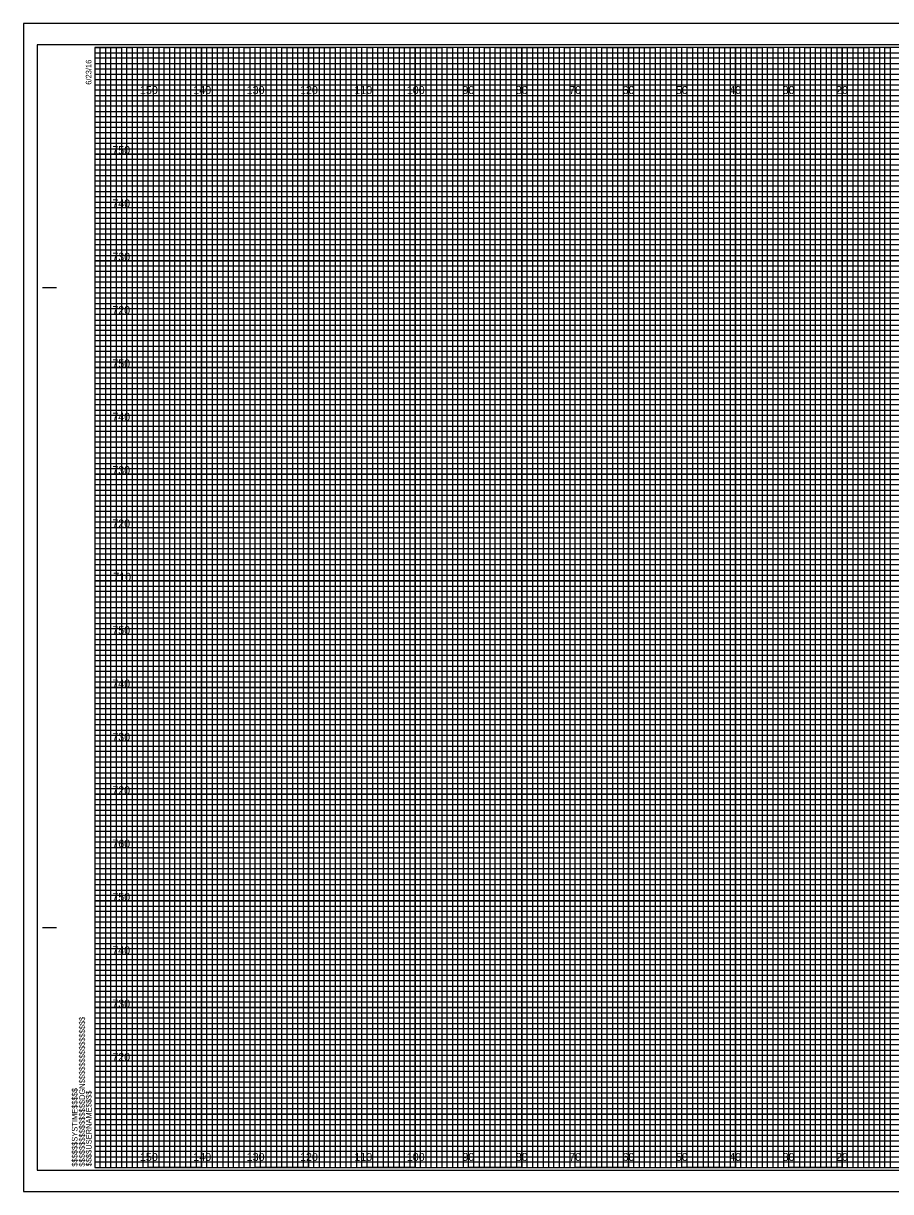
# Model space of a CAD drawing. Extents: x -13 to 323, y 655 to 874.
# Drawn here: x -13.4 to 149.1, y 655.5 to 874.5 of the extents above; entities that cross this region are included whole.
import ezdxf

# ---------------------------------------------------------------- set-up
doc = ezdxf.new("R2010")
doc.units = 0
for name, color, linetype in [('Prop CMT Guardrail Graphics', 7, 'Continuous'), ('Prop XS DDE', 7, 'Continuous'), ('Prop XS DDE Elevations', 7, 'Continuous'), ('Prop XS DDE Text', 7, 'Continuous'), ('Prop XS Hydro Elevations', 7, 'Continuous'), ('Prop XS Hydro Slope Text', 7, 'Continuous'), ('Prop XS Hydro Typical Ditch Data', 7, 'Continuous'), ('Prop XS SE Text', 7, 'Continuous'), ('Prop XS Undercut Exc', 7, 'Continuous'), ('Scratch_Level_1', 7, 'Continuous'), ('Scratch_Level_4', 7, 'Continuous')]:
    doc.layers.add(name, color=color, linetype=linetype)

msp = doc.modelspace()

# ---------------------------------------------------------------- linework, layer by layer
at = {"layer": 'Prop CMT Guardrail Graphics'}
for p, q in [((10, 870), (0, 870)), ((10, 660), (10, 870)), ((30, 870), (20, 870)), ((20, 870), (20, 660)), ((30, 660), (30, 870)), ((50, 870), (40, 870)), ((40, 870), (40, 660)), ((50, 660), (50, 870)), ((70, 870), (60, 870)), ((60, 870), (60, 660)), ((70, 660), (70, 870)), ((90, 870), (80, 870)), ((80, 870), (80, 660)), ((90, 660), (90, 870)), ((110, 870), (100, 870)), ((100, 870), (100, 660)), ((110, 660), (110, 870)), ((130, 870), (120, 870)), ((120, 870), (120, 660)), ((130, 660), (130, 870)), ((150, 870), (140, 870)), ((140, 870), (140, 660)), ((20, 660), (10, 660)), ((40, 660), (30, 660)), ((60, 660), (50, 660)), ((80, 660), (70, 660)), ((100, 660), (90, 660)), ((120, 660), (110, 660)), ((140, 660), (130, 660))]:
    msp.add_line(p, q, dxfattribs=at)
for points in [[(0, 860), (320, 860), (320, 850), (0, 850)], [(0, 840), (320, 840), (320, 830), (0, 830)], [(0, 820), (320, 820), (320, 810), (0, 810)], [(0, 800), (320, 800), (320, 790), (0, 790)], [(0, 780), (320, 780), (320, 770), (0, 770)], [(0, 760), (320, 760), (320, 750), (0, 750)], [(0, 740), (320, 740), (320, 730), (0, 730)], [(0, 720), (320, 720), (320, 710), (0, 710)], [(0, 700), (320, 700), (320, 690), (0, 690)], [(0, 680), (320, 680), (320, 670), (0, 670)]]:
    msp.add_lwpolyline(points, dxfattribs=at)
at = {"layer": 'Prop XS DDE'}
msp.add_lwpolyline([(-10.8, 659.5), (322.4, 659.5), (322.4, 870.5), (-10.8, 870.5)], close=True, dxfattribs=at)
at = {"layer": 'Prop XS DDE Elevations'}
for p, q in [((323.3, 874.5), (-13.4, 874.5)), ((-13.4, 874.5), (-13.4, 655.5)), ((-13.4, 655.5), (323.3, 655.5))]:
    msp.add_line(p, q, dxfattribs=at)
at = {"layer": 'Prop XS DDE Text'}
for p, q in [((10, 660), (10, 870)), ((20, 660), (20, 870)), ((30, 660), (30, 870)), ((40, 660), (40, 870)), ((50, 660), (50, 870)), ((60, 660), (60, 870)), ((70, 660), (70, 870)), ((80, 660), (80, 870)), ((90, 660), (90, 870)), ((100, 660), (100, 870)), ((110, 660), (110, 870)), ((120, 660), (120, 870)), ((130, 660), (130, 870)), ((140, 660), (140, 870)), ((0, 860), (320, 860)), ((0, 850), (320, 850)), ((0, 840), (320, 840)), ((0, 830), (320, 830)), ((0, 820), (320, 820)), ((0, 810), (320, 810)), ((0, 800), (320, 800)), ((0, 790), (320, 790)), ((0, 780), (320, 780)), ((0, 770), (320, 770)), ((0, 760), (320, 760)), ((0, 750), (320, 750)), ((0, 740), (320, 740)), ((0, 730), (320, 730)), ((0, 720), (320, 720)), ((0, 710), (320, 710)), ((0, 700), (320, 700)), ((0, 690), (320, 690)), ((0, 680), (320, 680)), ((0, 670), (320, 670))]:
    msp.add_line(p, q, dxfattribs=at)
at = {"layer": 'Prop XS Hydro Elevations'}
for points in [[(0, 660), (1, 660), (1, 870), (2, 870), (2, 660)], [(2, 660), (3, 660), (3, 870), (4, 870), (4, 660)], [(5, 660), (6, 660), (6, 870), (7, 870), (7, 660)], [(7, 660), (8, 660), (8, 870), (9, 870), (9, 660)], [(10, 660), (11, 660), (11, 870), (12, 870), (12, 660)], [(12, 660), (13, 660), (13, 870), (14, 870), (14, 660)], [(15, 660), (16, 660), (16, 870), (17, 870), (17, 660)], [(17, 660), (18, 660), (18, 870), (19, 870), (19, 660)], [(20, 660), (21, 660), (21, 870), (22, 870), (22, 660)], [(22, 660), (23, 660), (23, 870), (24, 870), (24, 660)], [(25, 660), (26, 660), (26, 870), (27, 870), (27, 660)], [(27, 660), (28, 660), (28, 870), (29, 870), (29, 660)], [(30, 660), (31, 660), (31, 870), (32, 870), (32, 660)], [(32, 660), (33, 660), (33, 870), (34, 870), (34, 660)], [(35, 660), (36, 660), (36, 870), (37, 870), (37, 660)], [(37, 660), (38, 660), (38, 870), (39, 870), (39, 660)], [(40, 660), (41, 660), (41, 870), (42, 870), (42, 660)], [(42, 660), (43, 660), (43, 870), (44, 870), (44, 660)], [(45, 660), (46, 660), (46, 870), (47, 870), (47, 660)], [(47, 660), (48, 660), (48, 870), (49, 870), (49, 660)], [(50, 660), (51, 660), (51, 870), (52, 870), (52, 660)], [(52, 660), (53, 660), (53, 870), (54, 870), (54, 660)], [(55, 660), (56, 660), (56, 870), (57, 870), (57, 660)], [(57, 660), (58, 660), (58, 870), (59, 870), (59, 660)], [(60, 660), (61, 660), (61, 870), (62, 870), (62, 660)], [(62, 660), (63, 660), (63, 870), (64, 870), (64, 660)], [(65, 660), (66, 660), (66, 870), (67, 870), (67, 660)], [(67, 660), (68, 660), (68, 870), (69, 870), (69, 660)], [(70, 660), (71, 660), (71, 870), (72, 870), (72, 660)], [(72, 660), (73, 660), (73, 870), (74, 870), (74, 660)], [(75, 660), (76, 660), (76, 870), (77, 870), (77, 660)], [(77, 660), (78, 660), (78, 870), (79, 870), (79, 660)], [(80, 660), (81, 660), (81, 870), (82, 870), (82, 660)], [(82, 660), (83, 660), (83, 870), (84, 870), (84, 660)], [(85, 660), (86, 660), (86, 870), (87, 870), (87, 660)], [(87, 660), (88, 660), (88, 870), (89, 870), (89, 660)], [(90, 660), (91, 660), (91, 870), (92, 870), (92, 660)], [(92, 660), (93, 660), (93, 870), (94, 870), (94, 660)], [(95, 660), (96, 660), (96, 870), (97, 870), (97, 660)], [(97, 660), (98, 660), (98, 870), (99, 870), (99, 660)], [(100, 660), (101, 660), (101, 870), (102, 870), (102, 660)], [(102, 660), (103, 660), (103, 870), (104, 870), (104, 660)], [(105, 660), (106, 660), (106, 870), (107, 870), (107, 660)], [(107, 660), (108, 660), (108, 870), (109, 870), (109, 660)], [(110, 660), (111, 660), (111, 870), (112, 870), (112, 660)], [(112, 660), (113, 660), (113, 870), (114, 870), (114, 660)], [(115, 660), (116, 660), (116, 870), (117, 870), (117, 660)], [(117, 660), (118, 660), (118, 870), (119, 870), (119, 660)], [(120, 660), (121, 660), (121, 870), (122, 870), (122, 660)], [(122, 660), (123, 660), (123, 870), (124, 870), (124, 660)], [(125, 660), (126, 660), (126, 870), (127, 870), (127, 660)], [(127, 660), (128, 660), (128, 870), (129, 870), (129, 660)], [(130, 660), (131, 660), (131, 870), (132, 870), (132, 660)], [(132, 660), (133, 660), (133, 870), (134, 870), (134, 660)], [(135, 660), (136, 660), (136, 870), (137, 870), (137, 660)], [(137, 660), (138, 660), (138, 870), (139, 870), (139, 660)], [(140, 660), (141, 660), (141, 870), (142, 870), (142, 660)], [(142, 660), (143, 660), (143, 870), (144, 870), (144, 660)], [(145, 660), (146, 660), (146, 870), (147, 870), (147, 660)], [(147, 660), (148, 660), (148, 870), (149, 870), (149, 660)]]:
    msp.add_lwpolyline(points, dxfattribs=at)
at = {"layer": 'Prop XS Hydro Slope Text'}
for p, q in [((-9.8, 825), (-7.3, 825)), ((-9.7, 825), (-7.2, 825)), ((-9.8, 705), (-7.3, 705)), ((-9.7, 705), (-7.2, 705)), ((0, 660), (0, 660)), ((0, 660), (0, 660)), ((0, 660), (0, 660)), ((0, 660), (0, 660)), ((0, 660), (0, 660)), ((0, 660), (0, 660)), ((0, 660), (0, 660))]:
    msp.add_line(p, q, dxfattribs=at)
msp.add_lwpolyline([(320, 870), (0, 870), (0, 660), (320, 660)], close=True, dxfattribs=at)
at = {"layer": 'Prop XS Hydro Typical Ditch Data'}
for p, q in [((0, 869), (260, 869)), ((260, 867.98), (0, 867.98)), ((0, 867.98), (0, 867)), ((0, 867), (260, 867)), ((260, 865.89), (0, 865.89)), ((0, 865.89), (0, 864)), ((0, 864), (320, 864))]:
    msp.add_line(p, q, dxfattribs=at)
for points in [[(0, 863), (270, 863), (320, 863), (320, 862), (0, 862)], [(0, 861), (320, 861), (320, 859), (0, 859)], [(0, 858), (320, 858), (320, 857), (0, 856.98)], [(0, 856), (320, 856), (320, 854), (0, 854)], [(0, 853), (320, 853), (320, 852), (0, 852)], [(0, 851), (320, 851), (320, 849), (0, 849)], [(0, 848), (320, 848), (320, 847), (0, 847)], [(0, 846), (320, 846), (320, 844), (0, 844)], [(0, 843), (320, 843), (320, 842), (0, 842)], [(0, 841), (320, 841), (320, 839), (0, 839)], [(0, 838), (320, 838), (320, 837), (0, 837)], [(0, 836), (320, 836), (320, 833.95), (320, 833), (320, 832), (0, 832)], [(0, 834), (320, 834), (320, 833), (0, 833)], [(0, 831), (320, 831), (320, 829), (0, 829.03)], [(0, 829.03), (320, 829), (320, 828), (0, 828)], [(0, 827), (320, 827), (320, 826), (0, 826)], [(0, 824), (320, 824), (320, 823), (0, 823)], [(0, 822), (320, 822), (320, 821), (0, 821)], [(-0.07, 818.89), (320, 818.89), (320, 817.88), (-0.07, 817.88)], [(0, 817), (320, 817), (320, 816), (0, 816)], [(0, 814), (320, 814), (320, 813), (0, 813)], [(0, 812), (320, 812), (320, 811), (0, 811)], [(0, 809), (320, 809), (320, 808), (0, 808)], [(0, 807), (320, 807), (320, 806), (0, 806)], [(0, 804), (320, 804), (320, 803), (0, 803)], [(0, 802), (320, 802), (320, 801), (0, 801)], [(0, 799), (320, 799), (319.99, 797.98), (0, 798)], [(0, 797), (320, 797), (320, 796), (0, 796)], [(0, 794), (320, 794), (320, 793), (0, 793)], [(0, 792), (320, 792), (320, 791), (0, 791)], [(0, 789), (320, 789), (320, 788), (0, 788)], [(0, 787), (320, 787), (320, 786), (0, 786)], [(0, 784), (320, 784), (320, 783), (0, 783)], [(0, 782), (320, 782), (320, 781), (0, 781)], [(0, 779), (320, 779), (320, 778), (0, 778)], [(0, 776.99), (320.07, 776.91), (320, 776), (0, 776)], [(0, 774), (320, 774), (320, 773), (0, 773)], [(0, 772), (320, 772), (320, 771), (0, 771)], [(0, 769), (320, 769), (320, 768), (0, 768)], [(0, 767), (320, 767), (320, 766), (0, 766)], [(0, 764), (320, 764), (320, 763), (0, 763)], [(0, 762), (320, 762), (320, 761), (0, 761)], [(0, 759), (320, 759), (320, 758), (0, 758)], [(0, 757), (320, 757), (320, 756), (0, 756)], [(0, 754), (320, 754), (320, 753), (0, 753)], [(0, 752), (320, 752), (320, 751), (0, 751)], [(0, 749), (320, 749), (320, 748), (0, 748)], [(0, 747), (320, 747), (320, 746), (0, 746)], [(0, 744), (320, 744), (320, 743), (0, 743)], [(0, 742), (320, 742), (320, 741), (0, 741)], [(0, 739), (320, 739), (319.99, 737.98), (0, 738)], [(0, 737), (320, 737), (320, 736), (0, 736)], [(0, 734), (320, 734), (320, 733), (0, 733)], [(0, 732), (320, 732), (320, 731), (0, 731)], [(0, 729), (320, 729), (320, 728), (0, 728)], [(0, 727), (320, 727), (320, 726), (0, 726)], [(0, 724), (320, 724), (320, 723), (0, 723)], [(0, 722), (320, 722), (320, 721), (0, 721)], [(0, 719), (320, 719), (320, 718), (0, 718)], [(0, 716.99), (320.07, 716.91), (320, 716), (0, 716)], [(0, 714), (320, 714), (320, 713), (0, 713)], [(0, 712), (320, 712), (320, 711), (0, 711)], [(0, 709), (320, 709), (320, 708), (0, 708)], [(0, 707), (320, 707), (320, 706), (0, 706)], [(0, 704), (320, 704), (320, 703), (0, 703)], [(0, 702), (320, 702), (320, 701), (0, 701)], [(0, 699), (320, 699), (320, 698), (0, 698)], [(0, 697), (320, 697), (320, 696), (0, 696)], [(0, 694), (320, 694), (320, 693), (0, 693)], [(0, 692), (320, 692), (320, 691), (0, 691)], [(0, 689), (320, 689), (320, 688), (0, 688)], [(0, 687), (320, 687), (320, 686), (0, 686)], [(0, 684), (320, 684), (320, 683), (0, 683)], [(0, 682), (320, 682), (320, 681), (0, 681)], [(0, 679), (320, 679), (320, 678), (0, 678)], [(0, 677), (320, 677), (320, 676), (0, 676)], [(0, 674), (320, 674), (320, 673), (0, 673)], [(0, 672), (320, 672), (320, 671), (0, 671)], [(0, 669), (320, 669), (320, 668), (0, 668)], [(0, 667), (320, 667), (320, 666), (0, 666)], [(0, 664), (320, 664), (320, 663), (0, 663)], [(0, 662), (320, 662), (320, 661), (0, 661)]]:
    msp.add_lwpolyline(points, dxfattribs=at)
at = {"layer": 'Prop XS Undercut Exc'}
msp.add_lwpolyline([(-13.4, 655.5), (323.3, 655.5), (323.3, 874.5), (-13.4, 874.5)], close=True, dxfattribs=at)
at = {"layer": 'Scratch_Level_4'}
for points in [[(0, 870), (5, 870), (5, 660), (15, 660), (15, 870), (25, 870), (25, 660), (35, 660), (35, 870), (45, 870), (45, 660), (55, 660), (55, 870), (65, 870), (65, 660), (75, 660), (75, 870), (85, 870), (85, 660), (95, 660), (95, 870), (105, 870), (105, 660), (115, 660), (115, 870), (125, 870), (125, 660), (135, 660), (135, 870), (145, 870), (145, 660), (155, 660)], [(0, 865), (275, 865)], [(0, 845), (320, 845), (320, 855), (0, 855)], [(0, 825), (320, 825), (320, 835), (0, 835)], [(0, 805), (320, 805), (320, 815), (0, 815)], [(0, 785), (320, 785), (320, 795), (0, 795)], [(0, 765), (320, 765), (320, 775), (0, 775)], [(0, 745), (320, 745), (320, 755), (0, 755)], [(0, 725), (320, 725), (320, 735), (0, 735)], [(0, 705), (320, 705), (320, 715), (0, 715)], [(0, 685), (320, 685), (320, 695), (0, 695)], [(0, 665), (320, 665), (320, 675), (0, 675)]]:
    msp.add_lwpolyline(points, dxfattribs=at)

# ---------------------------------------------------------------- texts
at = {"layer": 'Prop XS Hydro Slope Text'}
for s, p in [('6/23/16', (-0.65, 863)), ('$$$$$$$$$$$$$$$$DGN$$$$$$$$$$$$$$$$', (-1.88, 660.18)), ('$$$$$$SYSTIME$$$$$', (-3.26, 660.18)), ('$$$$USERNAME$$$$', (-0.62, 660.23))]:
    msp.add_text(s, height=1.05, rotation=90, dxfattribs=at).set_placement(p)
at = {"layer": 'Prop XS SE Text'}
for s, p in [('750', (3.26, 850)), ('740', (3.26, 840)), ('730', (3.26, 830)), ('720', (3.26, 820)), ('750', (3.26, 810)), ('740', (3.26, 800)), ('730', (3.26, 790)), ('720', (3.26, 780)), ('710', (3.44, 770)), ('750', (3.26, 760)), ('740', (3.26, 750)), ('730', (3.26, 740)), ('720', (3.26, 730)), ('760', (3.26, 720)), ('750', (3.26, 710)), ('740', (3.26, 700)), ('730', (3.26, 690)), ('720', (3.26, 680))]:
    msp.add_text(s, height=1.5, dxfattribs=at).set_placement(p)
at = {"layer": 'Scratch_Level_1'}
for s, p in [('150', (8.44, 861.25)), ('140', (18.44, 861.25)), ('130', (28.44, 861.25)), ('120', (38.44, 861.25)), ('110', (48.62, 861.25)), ('100', (58.44, 861.25)), ('90', (68.86, 861.25)), ('80', (78.86, 861.25)), ('70', (88.86, 861.25)), ('60', (98.86, 861.25)), ('50', (108.86, 861.25)), ('40', (118.86, 861.25)), ('30', (128.86, 861.25)), ('20', (138.86, 861.25)), ('150', (8.44, 661.25)), ('140', (18.44, 661.25)), ('130', (28.44, 661.25)), ('120', (38.44, 661.25)), ('110', (48.62, 661.25)), ('100', (58.44, 661.25)), ('90', (68.86, 661.25)), ('80', (78.86, 661.25)), ('70', (88.86, 661.25)), ('60', (98.86, 661.25)), ('50', (108.86, 661.25)), ('40', (118.86, 661.25)), ('30', (128.86, 661.25)), ('20', (138.86, 661.25))]:
    msp.add_text(s, height=1.5, dxfattribs=at).set_placement(p)

doc.saveas('drawing.dxf')
